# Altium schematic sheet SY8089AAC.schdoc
size 127 x 101 mm
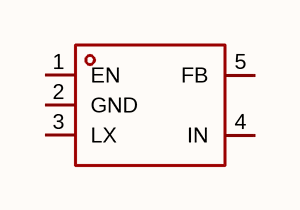
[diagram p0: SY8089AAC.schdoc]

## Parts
U?  sy8089aac  [SOT-23-5_L2.9-W1.6-P0.95-LS2.8-BL]  (value not drawn)

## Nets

Not connected (* = marked no-connect by the designer): U? 1(EN) 2(GND) 3(LX) 4(IN) 5(FB)

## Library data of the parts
U? = sy8089aac: 功能类型:降压型;工作电压:2.7V~5.5V;输出电压:-;输出电流:2A;输出类型:可调;; Manufacturer: Silergy(矽力杰); AddInBom: yes; ModelId: 018c57e721114987ae90467fe9f1d259; ModelTransform: 114.96,110.236,0,0,0,0,0,0,0; Function: 降压型; Output Current: 2A; Frequency - Switching: 1MHz; Synchronous Rectifier: 是; Number of Outputs: 1; Topology: 降压式; Quiescent Current: 55uA; Switch tube (built-in/external): 内置; Output Type: 可调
